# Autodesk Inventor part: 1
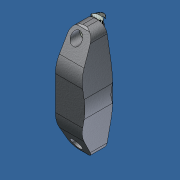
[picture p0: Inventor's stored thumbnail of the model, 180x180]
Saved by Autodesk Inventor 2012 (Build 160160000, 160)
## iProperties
Created: 2014-06
Part Number: 1
Material: Default
Document SubType Name: Modeling
Designer: Admin
Density: 1 g/cm^3
Mass: 37.1457 g
Surface Area: 173.364 cm^2
Volume: 37.1457 cm^3
Translation Standard: STEP AP214IS
FileName: 21_0949_0_1.stp
PreProcessor: ACIS
PostProcessor: Build: 160, Release: 2012 RTM - Date: Tue 03/01/2011
Sent Units: millimeter
Uncertainty: 1e-06
Author: Admin
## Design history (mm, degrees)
feature "Base1"
body "Solid1"
